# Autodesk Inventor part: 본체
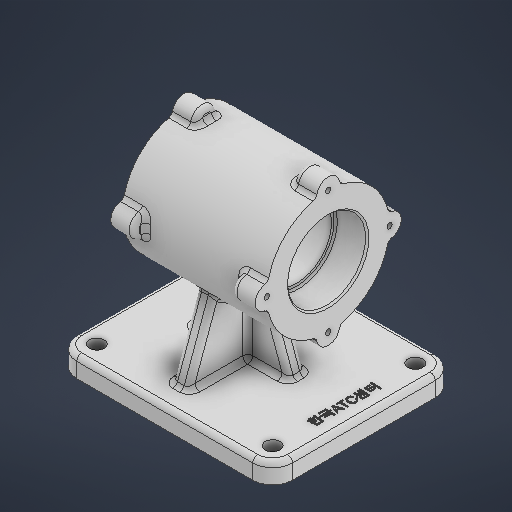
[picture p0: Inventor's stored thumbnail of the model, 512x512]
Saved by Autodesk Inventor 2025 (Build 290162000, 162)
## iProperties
Created: 2025-08
Part Number: 본체
Material: 일반
Document SubType Name: Modeling
Designer: infra10
Density: 1 g/cm^3
Appearance: 기본값
Author: infra10
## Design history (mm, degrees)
sketch "스케치2"
  geometry: L1 (65, -55)-(-65, -55); L2 (-65, -55)-(-65, 55); L3 (-65, 55)-(65, 55); L4 (65, 55)-(65, -55); L5 (65, -55)-(-65, 55); L6 (-65, -55)-(65, 55); 1 further point
  constraints: 12 end point, 2 midpoint, 2 parallel, 1 horizontal, 1 perpendicular
  dimensions: "d0" = 130 distance of L2.end L3.end; "d1" = 110 distance of L1.end L2.end
extrude "돌출1" new body sketch "스케치2" stored distance "d2" = 12; taper "d3" = 0 deg
sketch "스케치4"
  geometry: L1 (-6, -55)-(-6, 55) reference; C1 r 37 at (76, 0); 2 further points
  constraints: 1 centre point, 1 midpoint
  dimensions: "d4" = 74 diameter of C1; "d49" = 82 distance of point (-6, 0) C1.centre
extrude "돌출2" join sketch "스케치4" stored distance "d5" = 87; taper "d6" = 0 deg
sketch "스케치5"
  geometry: C1 r 7 at (0, 37); C2 r 7 at (-37, 0); C3 r 7 at (0, -37); C4 r 7 at (37, 0); 2 further points
  constraints: 4 centre point, 1 vertical alignment, 10 other
  dimensions: "d7" = 14 diameter of C1; "d10" = 360 deg dimension on point (0, 0) C1.centre (derived)
extrude "돌출3" join sketch "스케치5" distance "d12" = 14; taper "d13" = 0 deg
sketch "스케치6"
  geometry: A1 r 7 centre (0, 113) between (6.969, 112.338) and (-6.969, 112.338) reference; 6 further points
  constraints: 1 coincident, 5 other
  dimensions: "d21" = 37 distance of point (0, 76) point (0, 113); "d24" = 360 deg dimension on point (0, 76) point (0, 113) (derived)
  node "스케치 - 원형 패턴2" dims "d24" = 360 deg (derived)
hole "구멍1" sketch "스케치6" diameter "d14" = 42; stored, may be unused: countersink angle "d18" = 90 deg, drill point angle "d20" = 0 deg; dims "d15" = 8, "d16" = 47, "d17" = 19, "d19" = 10
hole "구멍2" sketch "스케치6" diameter "d26" = 3.242; stored, may be unused: countersink angle "d30" = 90 deg, drill point angle "d32" = 118 deg; dims "d27" = 8, "d28" = 47, "d29" = 19, "d31" = 10
fillet "모깎기1" dims "d33" = 3
fillet "모깎기2" dims "d34" = 1
chamfer "모따기1" distance "d35" = 1; stored, may be unused: second distance "d36" = 2, angle "d37" = 45 deg
sketch "스케치7"
  geometry: C1 r 21 at (0, 76) reference; 2 further points
  constraints: 1 coincident
hole "구멍3" sketch "스케치7" at (0, 76) diameter "d38" = 42; stored, may be unused: countersink angle "d42" = 90 deg, drill point angle "d44" = 118 deg; dims "d39" = 8, "d40" = 47, "d41" = 19, "d43" = 10
fillet "모깎기3" dims "d45" = 1
chamfer "모따기2" distance "d46" = 1; stored, may be unused: second distance "d47" = 2, angle "d48" = 45 deg
sketch "스케치13"
  geometry: L1 (53, -43)-(-53, -43); L2 (-53, -43)-(-53, 43); L3 (-53, 43)-(53, 43); L4 (53, 43)-(53, -43); L5 (53, -43)-(-53, 43); L6 (-53, -43)-(53, 43); 1 further point
  constraints: 12 end point, 2 midpoint, 2 parallel, 1 horizontal, 1 perpendicular
  dimensions: "d76" = 86 distance between parallel lines of L1 L3; "d77" = 106 distance between parallel lines of L4 L2
hole "구멍4" sketch "스케치13" at (-53, -43), (-53, 43), (53, 43), (53, -43) diameter "d78" = 9; stored, may be unused: countersink angle "d82" = 90 deg, drill point angle "d84" = 118 deg; dims "d79" = 6, "d80" = 47, "d81" = 19, "d83" = 8
fillet "모깎기4" dims "d85" = 12
fillet "모깎기6" dims "d88" = 3
node "작업 평면2"
sketch "스케치16"
  geometry: L1 (6, -38.5)-(6, -47.5) reference; L2 (49.036, -25.336)-(6, -41); L3 (-6, -55)-(3, -55) reference; L4 (39, 0)-(6, 0); L5 (6, 43)-(6, -43) reference; C1 r 1.621 at (39, 0) reference; A1 r 37 centre (76, 0) between (40.138, -9.104) and (66.896, -35.862) reference; 1 further point
  constraints: 4 end point, 1 midpoint, 1 point on circle, 1 point on line
  dimensions: "d110" = 14 distance from line of L2.end L3; "d111" = 110 deg angle of L1 L2
feature "리브5" sketch "스케치16" dims "d112" = 1, "d113" = 10, "d114" = 0, "d115" = 0, "d116" = 1, "d117" = 1
sketch "스케치18"
  geometry: L1 (-26.5, 39)-(26.5, 39) reference; L2 (53, 6)-(-53, 6) reference; L3 (12.989, 39)-(25, 6); L4 (0, 49.036)-(-10, 49.036) reference; 2 further points
  constraints: 2 end point, 2 point on line, 1 midpoint
  dimensions: "d118" = 30 horizontal distance of L3.end point (-5, 49.036); "d119" = 110 deg angle of L2 L3
feature "리브6" sketch "스케치18" dims "d120" = 1, "d121" = 10, "d122" = 0, "d123" = 0, "d124" = 1, "d125" = 1
node "작업 평면4"
sketch "스케치12" dims "d0" = 130, "d1" = 110
  geometry: L1 (27.509, -3.593)-(27.509, 3.593); L2 (27.509, 3.593)-(78.491, 3.593); L3 (78.491, 3.593)-(78.491, -3.593); L4 (78.491, -3.593)-(27.509, -3.593); L5 (65, 55)-(-65, 55) reference; L6 (65, -55)-(65, 55) reference; L7 (-10, 41)-(0, 41) reference; 6 further points
  constraints: 5 midpoint, 2 other
  dimensions: "d72" = 7.18601 distance between parallel lines of L4 L2; "d73" = 3.593 distance from line of L4 point (65, 0) (= 0.5 x d72); "d126" = 58 horizontal distance of point (-5, 41) point (53, -3.593)
feature "엠보싱1" sketch "스케치12" dims "d0" = 130, "d1" = 110, "d74" = 0.5, "d75" = 0
fillet "모깎기11" dims "d127" = 3
fillet "모깎기12" dims "d128" = 2
node "솔리드1"
mirror "미러1"
mirror "미러5"
mirror "미러6"
node "스케치 - 원형 패턴1" dims "d10" = 360 deg (derived)
node "작업 평면3"
feature "A9D066F2-1C7D-4E18-AEED-F7BC21143FA4" dims "d14" = 42, "d15" = 8, "d16" = 47, "d17" = 19, "d18" = 90 deg, "d19" = 10, "d20" = 0
other parameters: "d109" = -5
